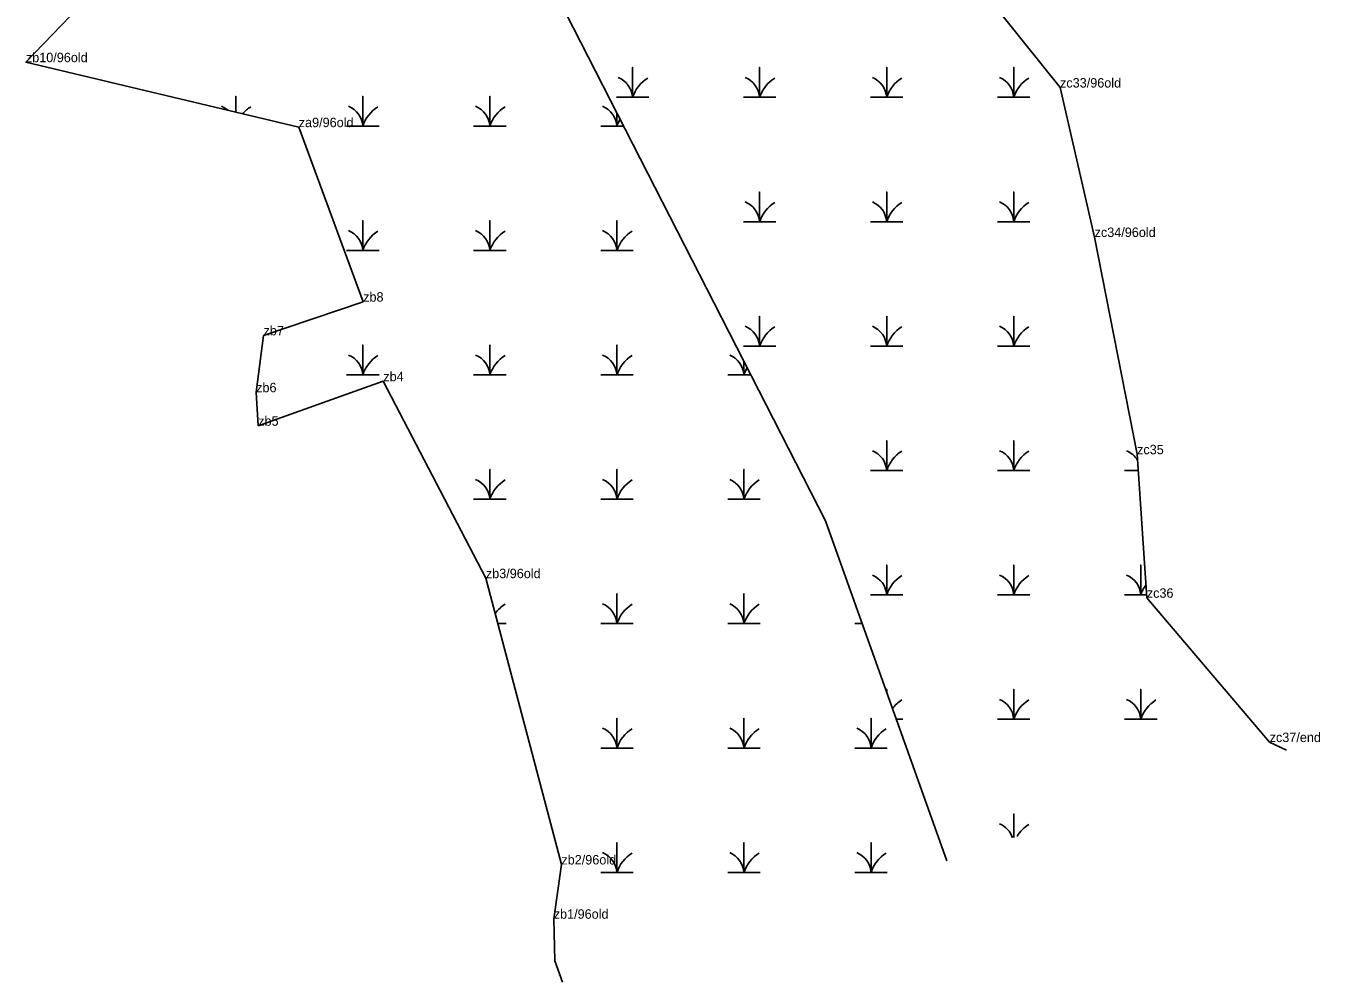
# Model space of a CAD drawing. Extents: x 2072529 to 2268796, y 436423 to 470406.
# Drawn here: x 2252087 to 2252772, y 437840 to 438346 of the extents above; entities that cross this region are included whole.
import ezdxf

# ---------------------------------------------------------------- set-up
doc = ezdxf.new("R2010")
doc.units = 0
for name, color, linetype in [('Exist Environmental Wetland Boundary Cogo Comment', 7, 'Continuous'), ('Exist Environmental Wetland Boundary Cogo Point CELL', 7, 'Continuous'), ('Old_Level_20', 7, 'Continuous'), ('Old_Level_52', 7, 'Continuous')]:
    doc.layers.add(name, color=color, linetype=linetype)

msp = doc.modelspace()

# ---------------------------------------------------------------- linework, layer by layer
at = {"layer": 'Exist Environmental Wetland Boundary Cogo Point CELL'}
for points in [[(2252399.77, 438308.05), (2252408.37, 438308.05), (2252408.37, 438323.83), (2252408.37, 438308.05), (2252416.97, 438308.05)], [(2252467.02, 438308.05), (2252475.62, 438308.05), (2252475.62, 438323.83), (2252475.62, 438308.05), (2252484.22, 438308.05)], [(2252534.27, 438308.05), (2252542.87, 438308.05), (2252542.87, 438323.83), (2252542.87, 438308.05), (2252551.47, 438308.05)], [(2252601.52, 438308.05), (2252610.12, 438308.05), (2252610.12, 438323.83), (2252610.12, 438308.05), (2252618.72, 438308.05)], [(2252198.33, 438300.2), (2252198.33, 438308.64), (2252198.33, 438300.2)], [(2252256.98, 438292.86), (2252265.58, 438292.86), (2252265.58, 438308.64), (2252265.58, 438292.86), (2252274.18, 438292.86)], [(2252324.23, 438292.86), (2252332.83, 438292.86), (2252332.83, 438308.64), (2252332.83, 438292.86), (2252341.43, 438292.86)], [(2252391.48, 438292.86), (2252400.08, 438292.86), (2252400.08, 438299.97)], [(2252400.08, 438299.97), (2252400.08, 438292.86), (2252403.72, 438292.86)], [(2252467.02, 438242.25), (2252475.62, 438242.25), (2252475.62, 438258.03), (2252475.62, 438242.25), (2252484.22, 438242.25)], [(2252534.27, 438242.25), (2252542.87, 438242.25), (2252542.87, 438258.03), (2252542.87, 438242.25), (2252551.47, 438242.25)], [(2252601.52, 438242.25), (2252610.12, 438242.25), (2252610.12, 438258.03), (2252610.12, 438242.25), (2252618.72, 438242.25)], [(2252256.98, 438227.06), (2252265.58, 438227.06), (2252265.58, 438242.84), (2252265.58, 438227.06), (2252274.18, 438227.06)], [(2252324.23, 438227.06), (2252332.83, 438227.06), (2252332.83, 438242.84), (2252332.83, 438227.06), (2252341.43, 438227.06)], [(2252391.48, 438227.06), (2252400.08, 438227.06), (2252400.08, 438242.84), (2252400.08, 438227.06), (2252408.68, 438227.06)], [(2252467.02, 438176.45), (2252475.62, 438176.45), (2252475.62, 438192.23), (2252475.62, 438176.45), (2252484.22, 438176.45)], [(2252534.27, 438176.45), (2252542.87, 438176.45), (2252542.87, 438192.23), (2252542.87, 438176.45), (2252551.47, 438176.45)], [(2252601.52, 438176.45), (2252610.12, 438176.45), (2252610.12, 438192.23), (2252610.12, 438176.45), (2252618.72, 438176.45)], [(2252256.98, 438161.26), (2252265.58, 438161.26), (2252265.58, 438177.04), (2252265.58, 438161.26), (2252274.18, 438161.26)], [(2252324.23, 438161.26), (2252332.83, 438161.26), (2252332.83, 438177.04), (2252332.83, 438161.26), (2252341.43, 438161.26)], [(2252391.48, 438161.26), (2252400.08, 438161.26), (2252400.08, 438177.04), (2252400.08, 438161.26), (2252408.68, 438161.26)], [(2252458.73, 438161.26), (2252467.33, 438161.26), (2252467.33, 438168.44)], [(2252467.33, 438168.44), (2252467.33, 438161.26), (2252471.01, 438161.26)], [(2252534.27, 438110.65), (2252542.87, 438110.65), (2252542.87, 438126.43), (2252542.87, 438110.65), (2252551.47, 438110.65)], [(2252601.52, 438110.65), (2252610.12, 438110.65), (2252610.12, 438126.43), (2252610.12, 438110.65), (2252618.72, 438110.65)], [(2252324.23, 438095.46), (2252332.83, 438095.46), (2252332.83, 438111.24), (2252332.83, 438095.46), (2252341.43, 438095.46)], [(2252391.48, 438095.46), (2252400.08, 438095.46), (2252400.08, 438111.24), (2252400.08, 438095.46), (2252408.68, 438095.46)], [(2252458.73, 438095.46), (2252467.33, 438095.46), (2252467.33, 438111.24), (2252467.33, 438095.46), (2252475.93, 438095.46)], [(2252668.77, 438110.65), (2252675.98, 438110.65)], [(2252534.27, 438044.85), (2252542.87, 438044.85), (2252542.87, 438060.63), (2252542.87, 438044.85), (2252551.47, 438044.85)], [(2252601.52, 438044.85), (2252610.12, 438044.85), (2252610.12, 438060.63), (2252610.12, 438044.85), (2252618.72, 438044.85)], [(2252668.77, 438044.85), (2252677.37, 438044.85), (2252677.37, 438060.63), (2252677.37, 438044.85), (2252680.45, 438044.85)], [(2252391.48, 438029.66), (2252400.08, 438029.66), (2252400.08, 438045.44), (2252400.08, 438029.66), (2252408.68, 438029.66)], [(2252458.73, 438029.66), (2252467.33, 438029.66), (2252467.33, 438045.44), (2252467.33, 438029.66), (2252475.93, 438029.66)], [(2252337.07, 438029.66), (2252341.43, 438029.66)], [(2252525.98, 438029.66), (2252529.88, 438029.66)], [(2252542.87, 437993.27), (2252542.87, 437994.83), (2252542.87, 437993.27)], [(2252601.52, 437979.05), (2252610.12, 437979.05), (2252610.12, 437994.83), (2252610.12, 437979.05), (2252618.72, 437979.05)], [(2252668.77, 437979.05), (2252677.37, 437979.05), (2252677.37, 437994.83), (2252677.37, 437979.05), (2252685.97, 437979.05)], [(2252391.48, 437963.86), (2252400.08, 437963.86), (2252400.08, 437979.64), (2252400.08, 437963.86), (2252408.68, 437963.86)], [(2252458.73, 437963.86), (2252467.33, 437963.86), (2252467.33, 437979.64), (2252467.33, 437963.86), (2252475.93, 437963.86)], [(2252525.98, 437963.86), (2252534.58, 437963.86), (2252534.58, 437979.64), (2252534.58, 437963.86), (2252543.18, 437963.86)], [(2252547.94, 437979.05), (2252551.47, 437979.05)], [(2252610.12, 437916.57), (2252610.12, 437929.03), (2252610.12, 437916.57)], [(2252391.48, 437898.06), (2252400.08, 437898.06), (2252400.08, 437913.84), (2252400.08, 437898.06), (2252408.68, 437898.06)], [(2252458.73, 437898.06), (2252467.33, 437898.06), (2252467.33, 437913.84), (2252467.33, 437898.06), (2252475.93, 437898.06)], [(2252525.98, 437898.06), (2252534.58, 437898.06), (2252534.58, 437913.84), (2252534.58, 437898.06), (2252543.18, 437898.06)]]:
    msp.add_lwpolyline(points, dxfattribs=at)
for centre, radius, start, end in [((2252396.1, 438307.17), 12.3, 4.14034, 67.53497), ((2252426.61, 438301.99), 19.22, 122.12745, 161.62219), ((2252463.35, 438307.17), 12.3, 4.14034, 67.53497), ((2252493.86, 438301.99), 19.22, 122.12745, 161.62219), ((2252530.6, 438307.17), 12.3, 4.14034, 67.53497), ((2252561.11, 438301.99), 19.22, 122.12745, 161.62219), ((2252597.85, 438307.17), 12.3, 4.14034, 67.53497), ((2252628.36, 438301.99), 19.22, 122.12745, 161.62219), ((2252186.07, 438291.97), 12.3, 48.53972, 67.53497), ((2252216.57, 438286.79), 19.22, 122.12745, 139.30029), ((2252253.32, 438291.97), 12.3, 4.14034, 67.53497), ((2252283.82, 438286.79), 19.22, 122.12745, 161.62219), ((2252320.57, 438291.97), 12.3, 4.14034, 67.53497), ((2252351.07, 438286.79), 19.22, 122.12745, 161.62219), ((2252387.82, 438291.97), 12.3, 4.14034, 67.53497), ((2252418.32, 438286.79), 19.22, 149.27882, 161.62219), ((2252463.35, 438241.37), 12.3, 4.14034, 67.53497), ((2252493.86, 438236.19), 19.22, 122.12745, 161.62219), ((2252530.6, 438241.37), 12.3, 4.14034, 67.53497), ((2252561.11, 438236.19), 19.22, 122.12745, 161.62219), ((2252597.85, 438241.37), 12.3, 4.14034, 67.53497), ((2252628.36, 438236.19), 19.22, 122.12745, 161.62219), ((2252253.32, 438226.17), 12.3, 4.14034, 67.53497), ((2252283.82, 438220.99), 19.22, 122.12745, 161.62219), ((2252320.57, 438226.17), 12.3, 4.14034, 67.53497), ((2252351.07, 438220.99), 19.22, 122.12745, 161.62219), ((2252387.82, 438226.17), 12.3, 4.14034, 67.53497), ((2252418.32, 438220.99), 19.22, 122.12745, 161.62219), ((2252463.35, 438175.57), 12.3, 4.14034, 67.53497), ((2252493.86, 438170.39), 19.22, 122.12745, 161.62219), ((2252530.6, 438175.57), 12.3, 4.14034, 67.53497), ((2252561.11, 438170.39), 19.22, 122.12745, 161.62219), ((2252597.85, 438175.57), 12.3, 4.14034, 67.53497), ((2252628.36, 438170.39), 19.22, 122.12745, 161.62219), ((2252253.32, 438160.37), 12.3, 4.14034, 67.53497), ((2252283.82, 438155.19), 19.22, 122.12745, 161.62219), ((2252320.57, 438160.37), 12.3, 4.14034, 67.53497), ((2252351.07, 438155.19), 19.22, 122.12745, 161.62219), ((2252387.82, 438160.37), 12.3, 4.14034, 67.53497), ((2252418.32, 438155.19), 19.22, 122.12745, 161.62219), ((2252455.07, 438160.37), 12.3, 4.14034, 67.53497), ((2252485.57, 438155.19), 19.22, 149.17318, 161.62219), ((2252530.6, 438109.77), 12.3, 4.14034, 67.53497), ((2252561.11, 438104.59), 19.22, 122.12745, 161.62219), ((2252597.85, 438109.77), 12.3, 4.14034, 67.53497), ((2252628.36, 438104.59), 19.22, 122.12745, 161.62219), ((2252665.1, 438109.77), 12.3, 31.28703, 67.53497), ((2252320.57, 438094.57), 12.3, 4.14034, 67.53497), ((2252351.07, 438089.39), 19.22, 122.12745, 161.62219), ((2252387.82, 438094.57), 12.3, 4.14034, 67.53497), ((2252418.32, 438089.39), 19.22, 122.12745, 161.62219), ((2252455.07, 438094.57), 12.3, 4.14034, 67.53497), ((2252485.57, 438089.39), 19.22, 122.12745, 161.62219), ((2252530.6, 438043.97), 12.3, 4.14034, 67.53497), ((2252561.11, 438038.79), 19.22, 122.12745, 161.62219), ((2252597.85, 438043.97), 12.3, 4.14034, 67.53497), ((2252628.36, 438038.79), 19.22, 122.12745, 161.62219), ((2252665.1, 438043.97), 12.3, 4.14034, 67.53497), ((2252695.61, 438038.79), 19.22, 143.85097, 161.62219), ((2252351.07, 438023.59), 19.22, 122.12745, 143.40047), ((2252387.82, 438028.77), 12.3, 4.14034, 67.53497), ((2252418.32, 438023.59), 19.22, 122.12745, 161.62219), ((2252455.07, 438028.77), 12.3, 4.14034, 67.53497), ((2252485.57, 438023.59), 19.22, 122.12745, 161.62219), ((2252561.11, 437972.99), 19.22, 122.12745, 142.26723), ((2252597.85, 437978.17), 12.3, 4.14034, 67.53497), ((2252628.36, 437972.99), 19.22, 122.12745, 161.62219), ((2252665.1, 437978.17), 12.3, 4.14034, 67.53497), ((2252695.61, 437972.99), 19.22, 122.12745, 161.62219), ((2252387.82, 437962.97), 12.3, 4.14034, 67.53497), ((2252418.32, 437957.79), 19.22, 122.12745, 161.62219), ((2252455.07, 437962.97), 12.3, 4.14034, 67.53497), ((2252485.57, 437957.79), 19.22, 122.12745, 161.62219), ((2252522.32, 437962.97), 12.3, 4.14034, 67.53497), ((2252552.82, 437957.79), 19.22, 122.12745, 161.62219), ((2252597.85, 437912.37), 12.3, 18.96283, 67.53497), ((2252628.36, 437907.19), 19.22, 122.12745, 148.83785), ((2252387.82, 437897.17), 12.3, 4.14034, 67.53497), ((2252418.32, 437891.99), 19.22, 122.12745, 161.62219), ((2252455.07, 437897.17), 12.3, 4.14034, 67.53497), ((2252485.57, 437891.99), 19.22, 122.12745, 161.62219), ((2252522.32, 437897.17), 12.3, 4.14034, 67.53497), ((2252552.82, 437891.99), 19.22, 122.12745, 161.62219)]:
    msp.add_arc(centre, radius, start, end, dxfattribs=at)
at = {"layer": 'Old_Level_20'}
for p, q in [((2252087.24, 438326.64), (2252087.24, 438326.64)), ((2252634.63, 438313.22), (2252634.63, 438313.22)), ((2252231.67, 438292.27), (2252231.67, 438292.27)), ((2252652.92, 438234.16), (2252652.92, 438234.16)), ((2252265.76, 438199.96), (2252265.76, 438199.96)), ((2252213.02, 438182.13), (2252213.02, 438182.13)), ((2252276.43, 438157.85), (2252276.43, 438157.85)), ((2252209.12, 438152.05), (2252209.12, 438152.05)), ((2252210.2, 438134.32), (2252210.2, 438134.32)), ((2252675.4, 438119.23), (2252675.4, 438119.23)), ((2252330.72, 438053.7), (2252330.72, 438053.7)), ((2252680.55, 438043.34), (2252680.55, 438043.34)), ((2252745.58, 437967.01), (2252745.58, 437967.01)), ((2252370.68, 437902.26), (2252370.68, 437902.26)), ((2252366.64, 437873.55), (2252366.64, 437873.55))]:
    msp.add_line(p, q, dxfattribs=at)
for points in [[(2252602.41, 438934.42), (2252617.06, 438839.42), (2252682.76, 438724.15), (2252702.34, 438698.78), (2252666.6, 438658.16), (2252617.07, 438534.58), (2252572.12, 438523.42), (2252588.63, 438438.61), (2252585.9, 438374.2), (2252634.63, 438313.22), (2252652.92, 438234.16), (2252675.4, 438119.23), (2252680.55, 438043.34), (2252745.58, 437967.01), (2252754.42, 437962.79)], [(2252129.61, 438370.68), (2252087.24, 438326.64), (2252231.67, 438292.27), (2252265.76, 438199.96), (2252213.02, 438182.13), (2252209.12, 438152.05), (2252210.2, 438134.32), (2252276.43, 438157.85), (2252330.72, 438053.7), (2252370.68, 437902.26), (2252366.64, 437873.55), (2252367.26, 437851.27), (2252371.21, 437840.04)]]:
    msp.add_lwpolyline(points, dxfattribs=at)
at = {"layer": 'Old_Level_52'}
for p, q in [((2252369.23, 438360.31), (2252510.45, 438084.11)), ((2252510.45, 438084.11), (2252574.64, 437904.25))]:
    msp.add_line(p, q, dxfattribs=at)

# ---------------------------------------------------------------- texts
at = {"layer": 'Exist Environmental Wetland Boundary Cogo Comment'}
for s, p in [('zb10/96old', (2252087.24, 438326.64)), ('zc33/96old', (2252634.63, 438313.22)), ('za9/96old', (2252231.67, 438292.27)), ('zc34/96old', (2252652.92, 438234.16)), ('zb8', (2252265.76, 438199.96)), ('zb7', (2252213.02, 438182.13)), ('zb4', (2252276.43, 438157.85)), ('zb6', (2252209.12, 438152.05)), ('zb5', (2252210.2, 438134.32)), ('zc35', (2252675.4, 438119.23)), ('zb3/96old', (2252330.72, 438053.7)), ('zc36', (2252680.55, 438043.34)), ('zc37/end', (2252745.58, 437967.01)), ('zb2/96old', (2252370.68, 437902.26)), ('zb1/96old', (2252366.64, 437873.55))]:
    msp.add_text(s, height=5, dxfattribs=at).set_placement(p)

doc.saveas('drawing.dxf')
